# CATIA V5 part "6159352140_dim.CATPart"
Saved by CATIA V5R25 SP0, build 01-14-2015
Part number: 6159352140_dim
Source: made
Property "PROI_CREATED_ON": "12/17/2008 9:21:37 AM"
Property "BLANK_DRAWING": "--"
Property "DRAWN_BY": "FPA"
Property "FINISH": "--"
Property "HEAT_TREATMENT": "ASSIGN"
Property "MATERIAL": "ASSIGN"
Property "PROJECT": "--"
Property "PROTOTYPE_NO": "--"
Property "RELATED_DRAWING": "--"
Property "COMPLETE_MATERIAL": "ASSIGN-ASSIGN"
Property "DESCRIPTION": "Q-SHIELD 500-S"
Property "DRAWING_EXIST": "--"
Property "MANUFACTURER": "--"
Property "MANUFACTURER_2": "--"
Property "MANUFACTURER_REF": "--"
Property "TYPE_PART": "--"
Property "TODAY_DATE": "2021/06/10"
Property "PDMREV": "01.0"
Property "PDMRL": "Production"
Property "PROI_REVISION": "01"
Property "PROI_VERSION": "0"
Property "PROI_RELEASE": "Production"
Property "PTC_MODIFIED": false
Property "MFG_WP_MATERIAL": "ASSIGN"
Property "COMPANY_CODE": "---"
Property "DESCRIPTION_JP": "--"
Property "PQP_DOCUMENT": "--"
Property "GHOST": false
Property "NO_PART": false
Property "PTC_WM_ITERATION": "0"
Property "PTC_WM_VERSION": "01.0"
Property "PTC_WM_CREATED_ON": "10-Jun-21 12:18:27 PM"
Property "PTC_WM_MODIFIED_ON": "10-Jun-21 03:21:17 PM"
Property "PTC_WM_NAME": "6159352140_dim.prt"
Property "PTC_WM_NUMBER": "6159352140_DIM.PRT"
Property "PTC_WM_LIFECYCLE_STATE": "Production"
Property "PTC_WM_LIFECYCLE": "Design_Process"
Property "PTC_WM_REVISION": "01"
Property "PTC_WM_CREATED_BY": "Florian Pavageau (Grefpav) (Grefpav: CPD)"
Property "PTC_WM_MODIFIED_BY": "Florian Pavageau (Grefpav) (Grefpav: CPD)"
Property "PTC_ORGANIZATION_ID": "CPD"
Property "PTC_WM_LOCATION": "/Products/TORQUE MEASUREMENT SYSTEMS/A2010 - DELTAWRENCH GEN2/9-01-Dimensional D"
Property "PTC_WM_PART_NAME": "6159352140_dim.prt"
Property "PTC_WM_PART_NUMBER": "6159352140_DIM"
Property "PTC_WM_TEAM": "Default"
Property "EXPORT_CONTROL": "NULL"
Property "PTC_COMMON_NAME": "6159352140_dim.prt"
Property "PTC_MASTER_MATERIAL": "ASSIGN"
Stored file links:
  d:\ptc\Echange\temp\6159352140_dim.CATPart

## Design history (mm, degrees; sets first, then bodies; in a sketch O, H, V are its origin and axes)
AxisSystem1 "CS0": origin (0, 0, 0), X (1, 0, 0), Y (0, 1, 0), Z (0, 0, 1)
Set1
  DatumSurface1 "Sheet.1"
  DatumSurface2 "Sheet.2"
  DatumSurface3 "Sheet.3"
  DatumSurface4 "Sheet.4"
  DatumSurface5 "Sheet.5"
  DatumSurface6 "Sheet.6"
  DatumSurface7 "Sheet.7"
  DatumSurface8 "Sheet.8"
  DatumSurface9 "Sheet.9"
  DatumSurface10 "Sheet.10"
  DatumSurface11 "Sheet.11"
  Plane1 "RIGHT": stored without definition
  Plane2 "TOP": stored without definition
  Plane3 "FRONT": stored without definition
Body1 "PartBody" (main body)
